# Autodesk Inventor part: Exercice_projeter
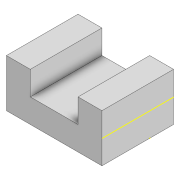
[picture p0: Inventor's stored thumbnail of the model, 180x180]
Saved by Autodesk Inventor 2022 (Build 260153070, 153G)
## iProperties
Created: 2021-05
Part Number: Exercice_projeter
Material: Générique
Document SubType Name: Modeling
Designer: Fabian
Density: 1 g/cm^3
Appearance: Par défaut
Author: Fabian
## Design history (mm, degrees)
sketch "Esquisse1"
  geometry: L1 (0, 0)-(0, 10); L2 (5, 10)-(10, 10); L3 (10, 10)-(10, 0); L4 (10, 0)-(-10, 0); L5 (-10, 0)-(-10, 10); L6 (-10, 10)-(-5, 10); L7 (-5, 10)-(-5, 5); L8 (-5, 5)-(5, 5); L9 (5, 5)-(5, 10)
  constraints: 18 end point, 5 perpendicular, 2 point on line, 2 vertical, 1 horizontal, 1 horizontal alignment, 1 midpoint, 1 other
  dimensions: "d4" = 10 distance of L4.end L5.end; "d5" = 5 distance of L6.end L7.end; "d6" = 20 distance of L3.end L4.end; "d7" = 10 distance of L7.end L8.end
extrude "Extrusion1" new body sketch "Esquisse1" distance "d8" = 10; taper "d10" = 0 deg; dims "d9" = 5, "d11" = 0
sketch "Esquisse2"
  geometry: L1 (15, 5)-(0, 5) reference; L2 (0, 5)-(15, 5) reference; 1 further point
  node "Boucle projetée1"
node "Solide1"
